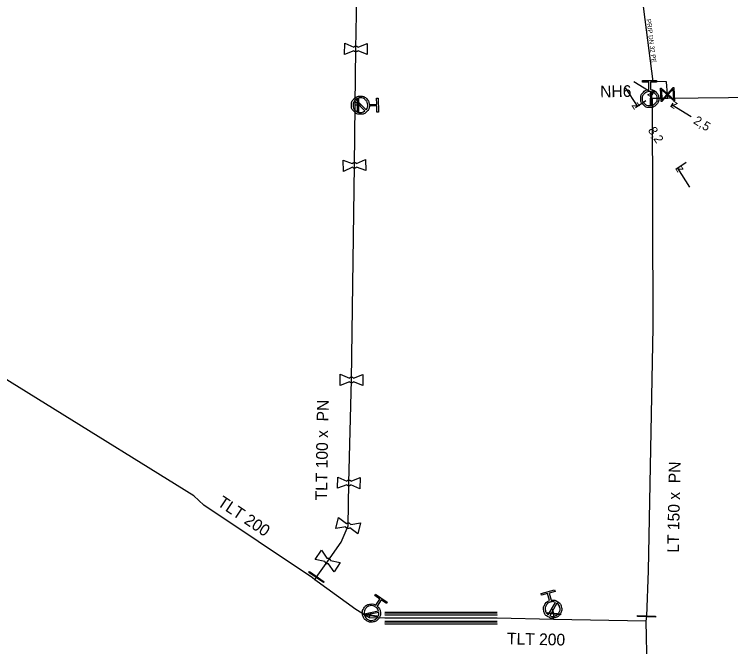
# Model space of a CAD drawing. Extents: x -643544 to -637295, y -1119190 to -1111715.
# Drawn here: x -641972.7 to -641893, y -1115526.7 to -1115456.3 of the extents above; entities that cross this region are included whole.
import ezdxf

# ---------------------------------------------------------------- set-up
doc = ezdxf.new("R2010")
doc.units = 0
for name, color, linetype in [('Default', 7, 'Continuous'), ('VP Chránička', 7, 'Continuous'), ('VP Chránička - okraje', 7, 'Continuous'), ('VP Hydrant', 7, 'Continuous'), ('VP Hydrant - popis', 7, 'Continuous'), ('VP Kótování', 7, 'Continuous'), ('VP Lomový bod', 7, 'Continuous'), ('VP Popis přípojky', 7, 'Continuous'), ('VP Přípojka', 7, 'Continuous'), ('VP Řad', 7, 'Continuous'), ('VP Řad - popis', 7, 'Continuous'), ('VP Šoupě', 7, 'Continuous')]:
    doc.layers.add(name, color=color, linetype=linetype)

msp = doc.modelspace()

# ---------------------------------------------------------------- linework, layer by layer
at = {"layer": 'Default'}
for points in [[(-641934.946, -1115459.915), (-641934.911, -1115459.875), (-641934.864, -1115459.848), (-641934.79, -1115459.807), (-641934.708, -1115459.808), (-641934.626, -1115459.808), (-641934.551, -1115459.851), (-641934.505, -1115459.877), (-641934.471, -1115459.917)], [(-641934.473, -1115460.326), (-641934.508, -1115460.365), (-641934.554, -1115460.392), (-641934.63, -1115460.433), (-641934.712, -1115460.432), (-641934.794, -1115460.432), (-641934.867, -1115460.39), (-641934.914, -1115460.363), (-641934.948, -1115460.323)], [(-641933.213, -1115466.474), (-641933.24, -1115466.834), (-641933.498, -1115467.093), (-641933.788, -1115467.387), (-641934.204, -1115467.39), (-641934.618, -1115467.393), (-641934.913, -1115467.102), (-641935.207, -1115466.812), (-641935.21, -1115466.396), (-641935.213, -1115465.984), (-641934.923, -1115465.688), (-641934.634, -1115465.393), (-641934.22, -1115465.39), (-641933.804, -1115465.387), (-641933.508, -1115465.676), (-641933.245, -1115465.931), (-641933.215, -1115466.291)], [(-641901.915, -1115464.646), (-641901.556, -1115464.673), (-641901.296, -1115464.931), (-641901.003, -1115465.222), (-641901.001, -1115465.638), (-641900.998, -1115466.052), (-641901.289, -1115466.346), (-641901.581, -1115466.64), (-641901.997, -1115466.643), (-641902.409, -1115466.645), (-641902.703, -1115466.355), (-641902.998, -1115466.065), (-641903.001, -1115465.651), (-641903.003, -1115465.235), (-641902.714, -1115464.94), (-641902.458, -1115464.677), (-641902.099, -1115464.647)], [(-641902.008, -1115464.828), (-641902.346, -1115464.83), (-641902.582, -1115465.069), (-641902.817, -1115465.308), (-641902.815, -1115465.646), (-641902.813, -1115465.984), (-641902.574, -1115466.219), (-641902.336, -1115466.455), (-641901.998, -1115466.453), (-641901.662, -1115466.451), (-641901.425, -1115466.212), (-641901.188, -1115465.973), (-641901.19, -1115465.636), (-641901.192, -1115465.298), (-641901.431, -1115465.062), (-641901.67, -1115464.826), (-641902.008, -1115464.828)], [(-641934.851, -1115465.887), (-641935.023, -1115466.105), (-641935.021, -1115466.394), (-641935.018, -1115466.73), (-641934.779, -1115466.967), (-641934.54, -1115467.203), (-641934.202, -1115467.201), (-641933.913, -1115467.198), (-641933.697, -1115467.023)], [(-641933.569, -1115466.893), (-641933.393, -1115466.675), (-641933.396, -1115466.382), (-641933.398, -1115466.044), (-641933.637, -1115465.808), (-641933.876, -1115465.573), (-641934.214, -1115465.576), (-641934.507, -1115465.578), (-641934.723, -1115465.757)], [(-641935.114, -1115472.895), (-641935.082, -1115472.854), (-641935.035, -1115472.825), (-641934.963, -1115472.781), (-641934.882, -1115472.778), (-641934.8, -1115472.775), (-641934.723, -1115472.815), (-641934.675, -1115472.838), (-641934.64, -1115472.877)], [(-641934.625, -1115473.286), (-641934.657, -1115473.326), (-641934.703, -1115473.355), (-641934.777, -1115473.399), (-641934.858, -1115473.402), (-641934.94, -1115473.405), (-641935.015, -1115473.367), (-641935.063, -1115473.341), (-641935.099, -1115473.302)], [(-641934.964, -1115497.177), (-641934.998, -1115497.216), (-641935.045, -1115497.242), (-641935.121, -1115497.283), (-641935.203, -1115497.282), (-641935.284, -1115497.282), (-641935.357, -1115497.24), (-641935.405, -1115497.212), (-641935.439, -1115497.172)], [(-641935.435, -1115496.764), (-641935.401, -1115496.724), (-641935.353, -1115496.698), (-641935.279, -1115496.657), (-641935.197, -1115496.658), (-641935.116, -1115496.658), (-641935.04, -1115496.702), (-641934.994, -1115496.728), (-641934.96, -1115496.768)], [(-641935.722, -1115508.23), (-641935.686, -1115508.191), (-641935.638, -1115508.165), (-641935.564, -1115508.126), (-641935.482, -1115508.128), (-641935.4, -1115508.13), (-641935.326, -1115508.174), (-641935.28, -1115508.201), (-641935.247, -1115508.242)], [(-641935.257, -1115508.651), (-641935.292, -1115508.689), (-641935.34, -1115508.715), (-641935.416, -1115508.754), (-641935.498, -1115508.752), (-641935.58, -1115508.75), (-641935.652, -1115508.707), (-641935.699, -1115508.679), (-641935.732, -1115508.638)], [(-641935.752, -1115512.946), (-641935.709, -1115512.915), (-641935.657, -1115512.9), (-641935.576, -1115512.877), (-641935.496, -1115512.896), (-641935.417, -1115512.916), (-641935.353, -1115512.975), (-641935.314, -1115513.011), (-641935.291, -1115513.058)], [(-641935.387, -1115513.455), (-641935.429, -1115513.485), (-641935.481, -1115513.5), (-641935.564, -1115513.523), (-641935.644, -1115513.504), (-641935.723, -1115513.484), (-641935.785, -1115513.427), (-641935.824, -1115513.389), (-641935.848, -1115513.342)], [(-641937.763, -1115517.432), (-641937.813, -1115517.446), (-641937.866, -1115517.443), (-641937.952, -1115517.436), (-641938.021, -1115517.392), (-641938.089, -1115517.347), (-641938.128, -1115517.272), (-641938.153, -1115517.224), (-641938.16, -1115517.171)], [(-641937.937, -1115516.83), (-641937.886, -1115516.815), (-641937.832, -1115516.818), (-641937.748, -1115516.824), (-641937.679, -1115516.868), (-641937.611, -1115516.913), (-641937.571, -1115516.99), (-641937.546, -1115517.037), (-641937.539, -1115517.09)], [(-641932.347, -1115522.149), (-641932.064, -1115522.373), (-641931.994, -1115522.732), (-641931.915, -1115523.137), (-641932.146, -1115523.483), (-641932.376, -1115523.827), (-641932.782, -1115523.907), (-641933.188, -1115523.988), (-641933.534, -1115523.756), (-641933.876, -1115523.527), (-641933.958, -1115523.122), (-641934.039, -1115522.716), (-641933.809, -1115522.372), (-641933.578, -1115522.026), (-641933.173, -1115521.944), (-641932.813, -1115521.87), (-641932.499, -1115522.047)], [(-641912.985, -1115521.496), (-641912.63, -1115521.429), (-641912.313, -1115521.611), (-641911.955, -1115521.816), (-641911.845, -1115522.218), (-641911.735, -1115522.617), (-641911.94, -1115522.976), (-641912.146, -1115523.335), (-641912.547, -1115523.445), (-641912.944, -1115523.554), (-641913.304, -1115523.35), (-641913.664, -1115523.146), (-641913.773, -1115522.747), (-641913.884, -1115522.346), (-641913.68, -1115521.986), (-641913.501, -1115521.666), (-641913.162, -1115521.544)], [(-641912.488, -1115521.732), (-641912.745, -1115521.618), (-641913.027, -1115521.696), (-641913.353, -1115521.785), (-641913.519, -1115522.077), (-641913.685, -1115522.368), (-641913.596, -1115522.694), (-641913.518, -1115522.977), (-641913.289, -1115523.139)], [(-641913.131, -1115523.229), (-641912.876, -1115523.339), (-641912.597, -1115523.263), (-641912.273, -1115523.174), (-641912.106, -1115522.882), (-641911.939, -1115522.59), (-641912.028, -1115522.264), (-641912.105, -1115521.985), (-641912.33, -1115521.822)], [(-641932.201, -1115522.679), (-641932.282, -1115522.41), (-641932.526, -1115522.248), (-641932.807, -1115522.06), (-641933.136, -1115522.125), (-641933.465, -1115522.191), (-641933.653, -1115522.472), (-641933.815, -1115522.716), (-641933.788, -1115522.995)], [(-641933.752, -1115523.173), (-641933.669, -1115523.438), (-641933.428, -1115523.599), (-641933.149, -1115523.786), (-641932.819, -1115523.721), (-641932.489, -1115523.656), (-641932.301, -1115523.375), (-641932.141, -1115523.134), (-641932.165, -1115522.857)]]:
    msp.add_open_spline(points, degree=3, dxfattribs=at)
at = {"layer": 'VP Chránička'}
for points in [[(-641931.479, -1115522.99), (-641918.979, -1115523.01)], [(-641931.481, -1115523.99), (-641918.981, -1115524.01)]]:
    msp.add_lwpolyline(points, dxfattribs=at)
at = {"layer": 'VP Chránička - okraje'}
for points in [[(-641931.479, -1115522.815), (-641918.979, -1115522.835)], [(-641918.979, -1115523.185), (-641931.479, -1115523.165)], [(-641931.481, -1115523.815), (-641918.981, -1115523.835)], [(-641918.981, -1115524.185), (-641931.481, -1115524.165)]]:
    msp.add_lwpolyline(points, dxfattribs=at)
at = {"layer": 'VP Hydrant'}
for points in [[(-641902.099, -1115464.647), (-641902.104, -1115463.827), (-641902.793, -1115463.831), (-641902.794, -1115463.647), (-641901.232, -1115463.638), (-641901.231, -1115463.821), (-641901.92, -1115463.826), (-641901.915, -1115464.646)], [(-641933.697, -1115467.023), (-641934.851, -1115465.887)], [(-641934.723, -1115465.757), (-641933.569, -1115466.893)], [(-641933.215, -1115466.291), (-641932.394, -1115466.284), (-641932.4, -1115465.595), (-641932.216, -1115465.593), (-641932.204, -1115467.156), (-641932.388, -1115467.157), (-641932.393, -1115466.468), (-641933.213, -1115466.474)], [(-641913.162, -1115521.544), (-641913.379, -1115520.753), (-641914.044, -1115520.936), (-641914.092, -1115520.759), (-641912.586, -1115520.345), (-641912.537, -1115520.522), (-641913.202, -1115520.705), (-641912.985, -1115521.496)], [(-641932.499, -1115522.047), (-641932.044, -1115521.365), (-641932.617, -1115520.982), (-641932.515, -1115520.829), (-641931.216, -1115521.697), (-641931.318, -1115521.85), (-641931.891, -1115521.467), (-641932.347, -1115522.149)], [(-641913.289, -1115523.139), (-641912.488, -1115521.732)], [(-641912.33, -1115521.822), (-641913.131, -1115523.229)], [(-641933.788, -1115522.995), (-641932.201, -1115522.679)], [(-641932.165, -1115522.857), (-641933.752, -1115523.173)]]:
    msp.add_lwpolyline(points, dxfattribs=at)
at = {"layer": 'VP Kótování'}
for points in [[(-641903.772, -1115463.749), (-641901.641, -1115465.056)], [(-641904.736, -1115464.442), (-641903.37, -1115466.536)], [(-641901.739, -1115465.216), (-641901.51, -1115464.843)], [(-641902.42, -1115465.916), (-641903.579, -1115466.673)], [(-641899.609, -1115466.524), (-641899.38, -1115466.151)], [(-641897.38, -1115467.671), (-641899.51, -1115466.364)], [(-641897.939, -1115472.783), (-641899.099, -1115473.54)], [(-641897.523, -1115475.497), (-641898.889, -1115473.403)]]:
    msp.add_lwpolyline(points, dxfattribs=at)
at = {"layer": 'VP Lomový bod'}
for points in [[(-641934.948, -1115460.323), (-641935.963, -1115460.738), (-641935.957, -1115459.488), (-641934.946, -1115459.915)], [(-641933.457, -1115459.502), (-641933.463, -1115460.752), (-641934.473, -1115460.326)], [(-641934.471, -1115459.917), (-641933.457, -1115459.502)], [(-641935.099, -1115473.302), (-641936.096, -1115473.761), (-641936.142, -1115472.512), (-641935.114, -1115472.895)], [(-641934.64, -1115472.877), (-641933.644, -1115472.419)], [(-641933.644, -1115472.419), (-641933.598, -1115473.668), (-641934.625, -1115473.286)], [(-641935.439, -1115497.172), (-641936.455, -1115497.585), (-641936.445, -1115496.335), (-641935.435, -1115496.764)], [(-641933.945, -1115496.355), (-641933.955, -1115497.605), (-641934.964, -1115497.177)], [(-641934.96, -1115496.768), (-641933.945, -1115496.355)], [(-641935.732, -1115508.638), (-641936.756, -1115509.033), (-641936.724, -1115507.783), (-641935.722, -1115508.23)], [(-641934.224, -1115507.847), (-641934.256, -1115509.097), (-641935.257, -1115508.651)], [(-641935.247, -1115508.242), (-641934.224, -1115507.847)], [(-641935.848, -1115513.342), (-641936.932, -1115513.513), (-641936.637, -1115512.298), (-641935.752, -1115512.946)], [(-641934.208, -1115512.887), (-641934.503, -1115514.102), (-641935.387, -1115513.455)], [(-641935.291, -1115513.058), (-641934.208, -1115512.887)], [(-641938.16, -1115517.171), (-641939.238, -1115516.969), (-641938.555, -1115515.923), (-641937.937, -1115516.83)], [(-641937.539, -1115517.09), (-641936.462, -1115517.291)], [(-641936.462, -1115517.291), (-641937.145, -1115518.337), (-641937.763, -1115517.432)]]:
    msp.add_lwpolyline(points, dxfattribs=at)
at = {"layer": 'VP Přípojka'}
for points in [[(-641899.981, -1115465.636), (-641900.02, -1115465.19), (-641900.119, -1115463.786), (-641901.624, -1115463.756), (-641902.639, -1115455.678), (-641903.36, -1115449.94), (-641902.99, -1115437.28), (-641903.21, -1115426.52), (-641903.46, -1115422.35), (-641903.94, -1115419.324)], [(-641902.001, -1115465.643), (-641901.874, -1115465.647), (-641901.748, -1115465.652)], [(-641934.21, -1115466.39), (-641934.47, -1115466.39), (-641934.79, -1115466.38)], [(-641912.73, -1115523.64), (-641912.67, -1115522.99), (-641912.81, -1115522.48)], [(-641933.18, -1115523.45), (-641933.135, -1115523.164), (-641932.976, -1115522.926)]]:
    msp.add_lwpolyline(points, dxfattribs=at)
at = {"layer": 'VP Řad'}
for points in [[(-641951.63, -1115510.91), (-641952.768, -1115509.884), (-641985.815, -1115489.4), (-642008.418, -1115475.862), (-642025.244, -1115464.652), (-642042.862, -1115452.451), (-642117.186, -1115406.218), (-642118.16, -1115405.62)], [(-641939.28, -1115519.21), (-641939.09, -1115518.92), (-641938.95, -1115518.7), (-641937.85, -1115517.13), (-641936.34, -1115515.02), (-641935.57, -1115513.2), (-641935.49, -1115508.44), (-641935.2, -1115496.97), (-641934.87, -1115473.09), (-641934.79, -1115466.38), (-641934.71, -1115460.12), (-641934.6, -1115454.3)], [(-641871.27, -1115465.76), (-641872.608, -1115465.768), (-641873.239, -1115465.708), (-641883.066, -1115465.451), (-641899.981, -1115465.636), (-641901.748, -1115465.652), (-641901.659, -1115491.082), (-641902.166, -1115518.234), (-641902.369, -1115523.288), (-641902.42, -1115523.83)], [(-641902.42, -1115523.83), (-641912.73, -1115523.64), (-641918.98, -1115523.51), (-641931.48, -1115523.49), (-641933.18, -1115523.45), (-641934.72, -1115522.51), (-641939.02, -1115519.42), (-641939.28, -1115519.21), (-641939.55, -1115519.02), (-641951.63, -1115510.91)], [(-641902.42, -1115523.83), (-641902.339, -1115529.097), (-641902.24, -1115536.25), (-641902.34, -1115541.1), (-641902.54, -1115552.54), (-641902.577, -1115564.213), (-641902.6, -1115564.53)]]:
    msp.add_lwpolyline(points, dxfattribs=at)
at = {"layer": 'VP Šoupě'}
for points in [[(-641899.312, -1115464.4), (-641899.23, -1115465.898), (-641899.296, -1115465.901), (-641899.389, -1115465.812), (-641900.015, -1115465.253), (-641900.662, -1115465.976), (-641900.728, -1115465.98), (-641900.81, -1115464.482), (-641900.744, -1115464.479), (-641900.022, -1115465.128), (-641899.462, -1115464.502), (-641899.378, -1115464.404), (-641899.312, -1115464.4)], [(-641899.397, -1115464.562), (-641899.956, -1115465.187), (-641899.332, -1115465.745), (-641899.397, -1115464.562)], [(-641901.777, -1115464.9), (-641901.833, -1115466.399), (-641901.927, -1115466.396), (-641901.871, -1115464.897), (-641901.777, -1115464.9)], [(-641900.642, -1115465.823), (-641900.081, -1115465.194), (-641900.708, -1115464.634), (-641900.642, -1115465.823)], [(-641934.517, -1115467.14), (-641934.517, -1115465.64), (-641934.423, -1115465.64), (-641934.423, -1115467.14), (-641934.517, -1115467.14)], [(-641938.3, -1115519.536), (-641939.95, -1115518.407), (-641939.88, -1115518.304), (-641938.23, -1115519.433), (-641938.3, -1115519.536)], [(-641933.868, -1115523.002), (-641932.387, -1115523.235), (-641932.401, -1115523.327), (-641933.883, -1115523.094), (-641933.868, -1115523.002)], [(-641913.412, -1115522.874), (-641911.919, -1115523.012), (-641911.927, -1115523.105), (-641913.421, -1115522.967), (-641913.412, -1115522.874)], [(-641903.365, -1115523.185), (-641901.367, -1115523.266), (-641901.372, -1115523.391), (-641903.37, -1115523.31), (-641903.365, -1115523.185)]]:
    msp.add_lwpolyline(points, dxfattribs=at)

# ---------------------------------------------------------------- texts
at = {"layer": 'VP Hydrant - popis'}
msp.add_text('NH6', height=1.3, rotation=1, dxfattribs=at).set_placement((-641907.509, -1115465.517))
at = {"layer": 'VP Kótování'}
for s, rotation, p in [('z', 328.46763, (-641902.329, -1115465.221)), ('z', 303.12358, (-641904.062, -1115466.39)), ('z', 148.46763, (-641898.823, -1115466.199)), ('2,5', 328.46763, (-641897.215, -1115468.359)), ('8,2', 303.12358, (-641902.241, -1115469.181)), ('z', 123.12358, (-641898.197, -1115473.549))]:
    msp.add_text(s, height=1, rotation=rotation, dxfattribs=at).set_placement(p)
at = {"layer": 'VP Popis přípojky'}
msp.add_text('PRIP DN 32 PE', height=0.5, rotation=277.16168, dxfattribs=at).set_placement((-641902.368, -1115456.831))
at = {"layer": 'VP Řad - popis'}
for s, rotation, p in [('TLT 100 x  PN ', 89.03714, (-641937.928, -1115510.393)), ('LT 150 x  PN ', 88.93027, (-641898.759, -1115516.212)), ('TLT 200', 326.25644, (-641950.221, -1115510.881)), ('TLT 200', 358.8084, (-641917.902, -1115526.409))]:
    msp.add_text(s, height=1.3, rotation=rotation, dxfattribs=at).set_placement(p)

doc.saveas('drawing.dxf')
